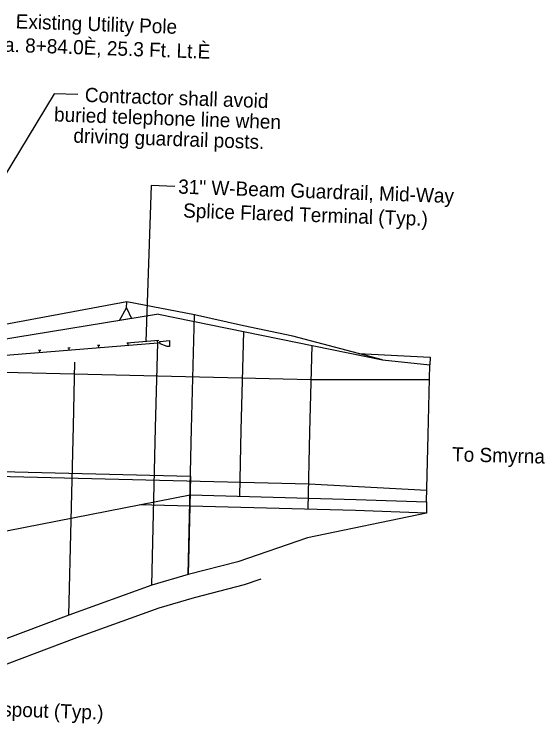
# Model space of a CAD drawing. Extents: x 2191309 to 2193046, y 863659 to 865133.
# Drawn here: x 2192785.4 to 2192897.5, y 863862.7 to 864012.5 of the extents above; entities that cross this region are included whole.
import ezdxf

# ---------------------------------------------------------------- set-up
doc = ezdxf.new("R2010")
doc.units = 0
for name, color, linetype in [('ANNOTATION', 7, 'Continuous'), ('D_Guardrail_End_MidSplice', 7, 'Continuous'), ('D_Roadway_Drive_Gravel', 7, 'Continuous'), ('D_Roadway_Edge_Shoulder', 7, 'Continuous'), ('D_Slope_ClearingLimitLine', 7, 'Continuous'), ('D_Slope_Direction', 7, 'Continuous'), ('D_Slope_Toe', 7, 'Continuous'), ('DIMENSIONS', 7, 'Continuous'), ('JUNK', 7, 'Continuous')]:
    doc.layers.add(name, color=color, linetype=linetype)

msp = doc.modelspace()

# ---------------------------------------------------------------- linework, layer by layer
at = {"layer": 'ANNOTATION'}
msp.add_lwpolyline([(2192819.29, 863976.15), (2192814.29, 863976.32), (2192813.16, 863943.43)], dxfattribs=at)
at = {"layer": 'D_Guardrail_End_MidSplice'}
for p, q in [((2192778.32, 863940.06), (2192815.69, 863943.14)), ((2192809.18, 863943.1), (2192815.9, 863943.66)), ((2192809.18, 863943.1), (2192809.67, 863943.14)), ((2192809.47, 863942.63), (2192809.42, 863943.12)), ((2192815.4, 863943.62), (2192815.9, 863943.66)), ((2192815.69, 863943.14), (2192815.65, 863943.64)), ((2192815.69, 863943.14), (2192816.19, 863943.18)), ((2192816.17, 863943.43), (2192818.21, 863943.6)), ((2192816.21, 863942.93), (2192816.17, 863943.43)), ((2192817.68, 863942.36), (2192816.21, 863942.93)), ((2192818.21, 863943.6), (2192818.18, 863942.35)), ((2192790.49, 863941.56), (2192790.99, 863941.6)), ((2192790.78, 863941.08), (2192790.74, 863941.58)), ((2192796.72, 863942.08), (2192797.22, 863942.12)), ((2192797.01, 863941.6), (2192796.97, 863942.1)), ((2192802.95, 863942.59), (2192803.44, 863942.63)), ((2192803.24, 863942.11), (2192803.2, 863942.61)), ((2192818.18, 863942.35), (2192817.68, 863942.36))]:
    msp.add_line(p, q, dxfattribs=at)
at = {"layer": 'D_Roadway_Drive_Gravel'}
for points in [[(2192858.12, 863940.89), (2192873.26, 863940.06), (2192873.22, 863938.5)], [(2192872.51, 863909.56), (2192872.45, 863907.14), (2192857.5, 863907.75), (2192811.8, 863908.9)]]:
    msp.add_lwpolyline(points, dxfattribs=at)
at = {"layer": 'D_Roadway_Edge_Shoulder'}
for p, q in [((2192815.84, 863949.14), (2192778.4, 863943.05)), ((2192872.86, 863923.73), (2192873.22, 863938.5)), ((2192872.51, 863909.56), (2192872.86, 863923.73))]:
    msp.add_line(p, q, dxfattribs=at)
for points in [[(2192815.84, 863949.14), (2192863.16, 863939.56), (2192873.22, 863938.5)], [(2192747.83, 863937.8), (2192848.13, 863935.34), (2192873.14, 863935.41)], [(2192722.33, 863910.66), (2192722.56, 863917.42), (2192822.63, 863914.96), (2192822.47, 863908.63)], [(2192747.18, 863915.81), (2192847.59, 863913.35), (2192872.57, 863912.05)], [(2192776.88, 863902.08), (2192822.53, 863911), (2192857.62, 863910.07), (2192872.51, 863909.56)]]:
    msp.add_lwpolyline(points, dxfattribs=at)
at = {"layer": 'D_Slope_ClearingLimitLine'}
msp.add_lwpolyline([(2192778.06, 863873.18), (2192798.63, 863880.91), (2192815.99, 863887.18), (2192823.44, 863889.37), (2192834.04, 863892.08), (2192837.57, 863893.29)], dxfattribs=at)
at = {"layer": 'D_Slope_Direction'}
for p, q in [((2192809.12, 863950.53), (2192809.16, 863951.79)), ((2192822.47, 863908.63), (2192822.12, 863894.2))]:
    msp.add_line(p, q, dxfattribs=at)
msp.add_lwpolyline([(2192807.64, 863947.8), (2192809.12, 863950.53), (2192809.12, 863950.53), (2192810.18, 863948.22)], close=True, dxfattribs=at)
at = {"layer": 'D_Slope_Toe'}
for points in [[(2192863.16, 863939.56), (2192844.23, 863944.54), (2192833.83, 863946.69), (2192823.46, 863949.01), (2192809.16, 863951.79), (2192778.47, 863946.05), (2192773.38, 863946.18), (2192748.39, 863946.79), (2192741.14, 863949.81), (2192723.71, 863950.96), (2192714.04, 863951.04)], [(2192872.45, 863907.14), (2192847.31, 863901.92), (2192832.61, 863896.88), (2192822.12, 863894.2), (2192814.44, 863891.94), (2192796.9, 863885.6), (2192776.3, 863877.86), (2192772.03, 863891.16), (2192747.06, 863892.87)]]:
    msp.add_lwpolyline(points, dxfattribs=at)
at = {"layer": 'DIMENSIONS'}
msp.add_lwpolyline([(2192798.8, 863995.53), (2192793.81, 863995.7), (2192760.59, 863940.86)], dxfattribs=at)
at = {"layer": 'JUNK'}
for p, q in [((2192822.87, 863924.96), (2192823.46, 863949.01)), ((2192833.8, 863945.5), (2192833.29, 863924.7)), ((2192815.25, 863925.14), (2192815.69, 863943.14)), ((2192847.86, 863924.34), (2192848.31, 863942.56)), ((2192797.88, 863925.57), (2192798.21, 863939.02)), ((2192796.9, 863885.6), (2192797.88, 863925.57)), ((2192814.44, 863891.94), (2192815.25, 863925.14)), ((2192822.12, 863894.2), (2192822.87, 863924.96)), ((2192833.29, 863924.7), (2192832.95, 863910.72)), ((2192847.46, 863908), (2192847.86, 863924.34))]:
    msp.add_line(p, q, dxfattribs=at)

# ---------------------------------------------------------------- texts
at = {"layer": 'ANNOTATION'}
for s, rotation, p in [('Existing Utility Pole', 358.0343, (2192785.66, 864009.5)), ('Sta. 8+84.0È, 25.3 Ft. Lt.È', 358.0343, (2192779.4, 864004.7)), ('Contractor shall avoid', 358.0343, (2192800.26, 863993.98)), ('buried telephone line when', 358.0343, (2192793.76, 863989.86)), ('driving guardrail posts.', 358.0343, (2192797.84, 863985.39)), ('31" W-Beam Guardrail, Mid-Way', 358.0343, (2192819.99, 863974.62)), ('Splice Flared Terminal (Typ.)', 358.0343, (2192821.03, 863969.57)), ('To Smyrna', 358.5937, (2192877.86, 863918.11)), ('Riprap Downspout (Typ.)', 358.0343, (2192759.63, 863865.09))]:
    msp.add_text(s, height=3, rotation=rotation, dxfattribs=at).set_placement(p)

doc.saveas('drawing.dxf')
